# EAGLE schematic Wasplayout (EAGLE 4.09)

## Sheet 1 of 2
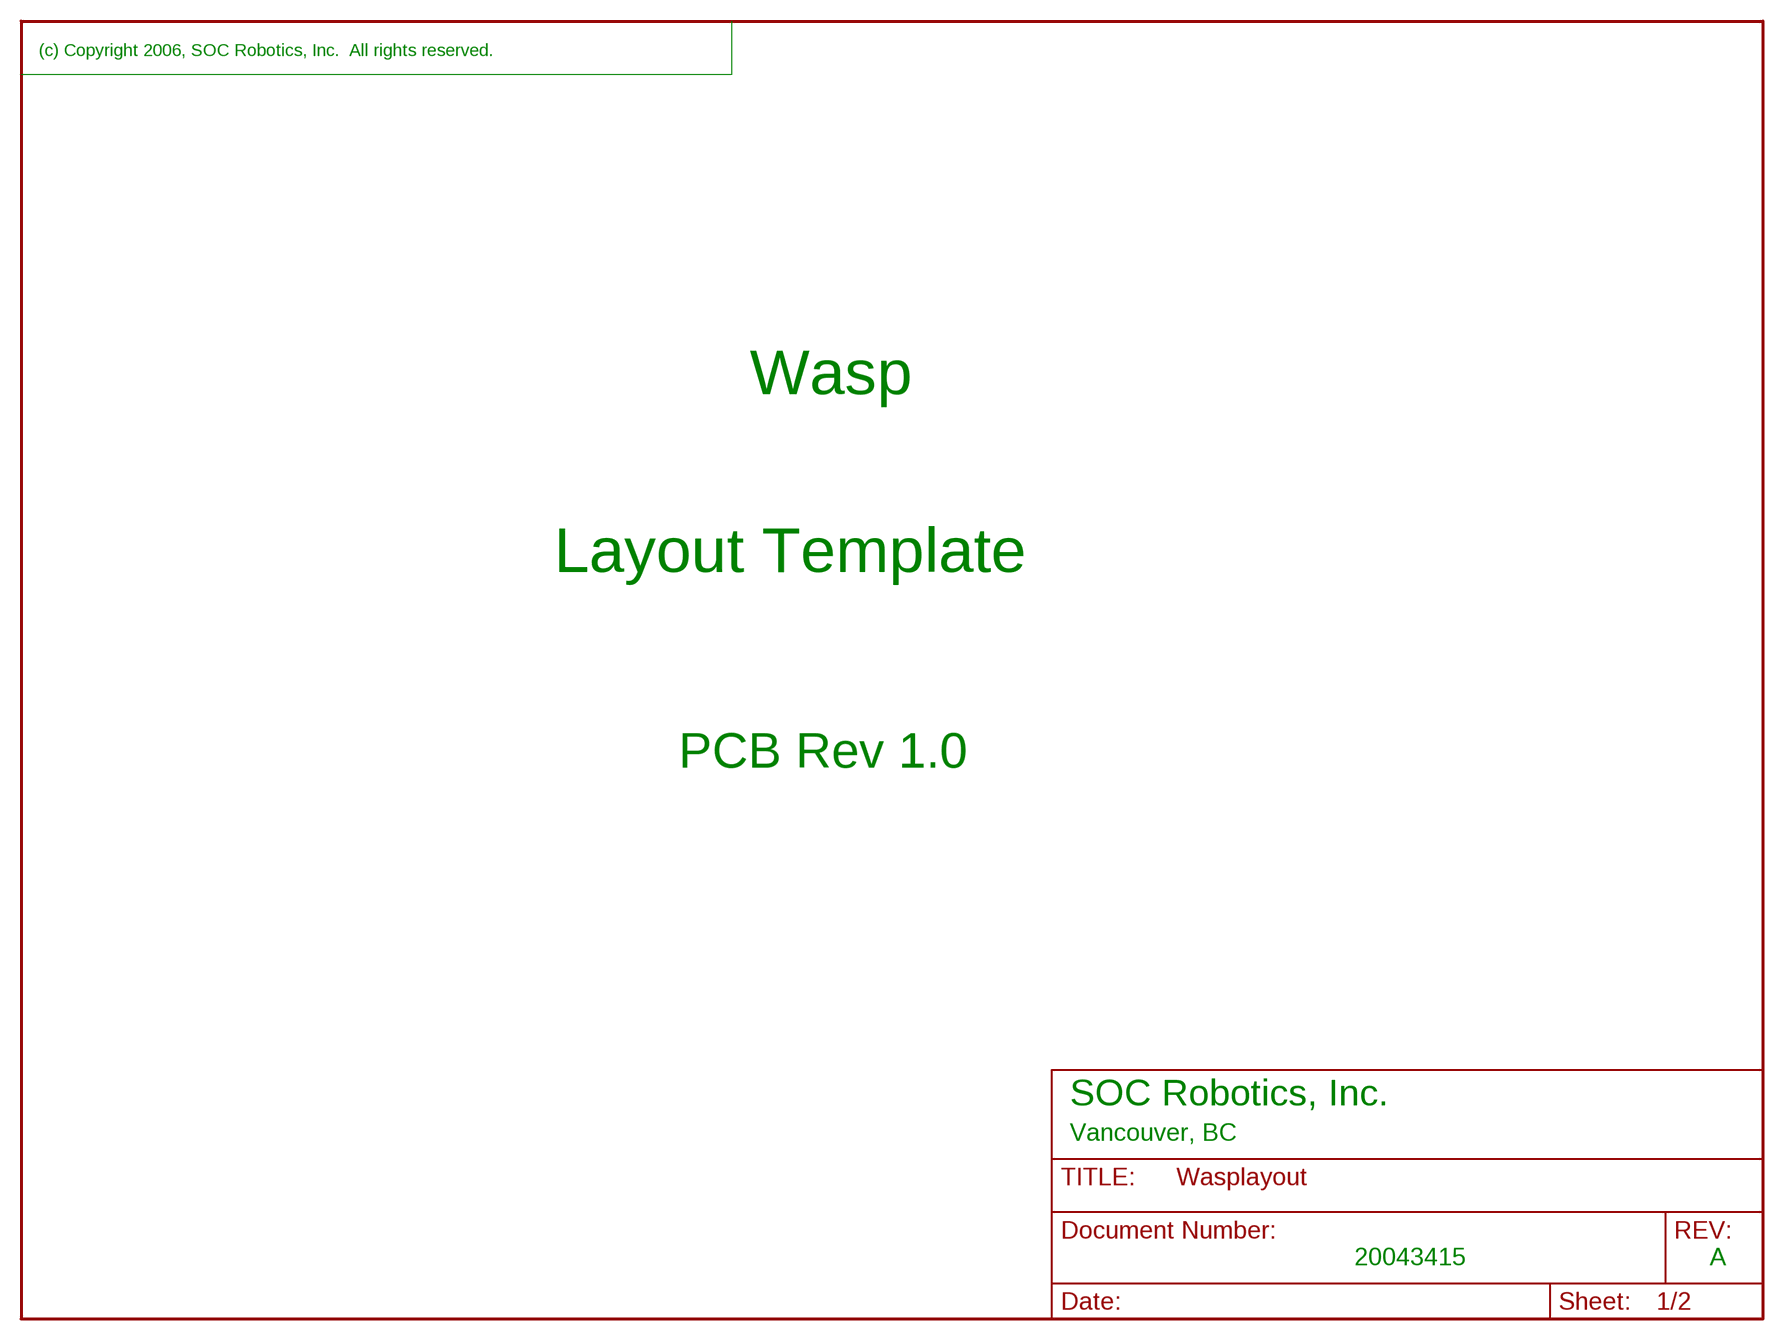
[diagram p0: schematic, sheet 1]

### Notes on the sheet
- (c) Copyright 2006, SOC Robotics, Inc.  All rights reserved.
- Wasp
- Layout Template
- PCB Rev 1.0
- SOC Robotics, Inc.
- Vancouver, BC
- 20043415 | A

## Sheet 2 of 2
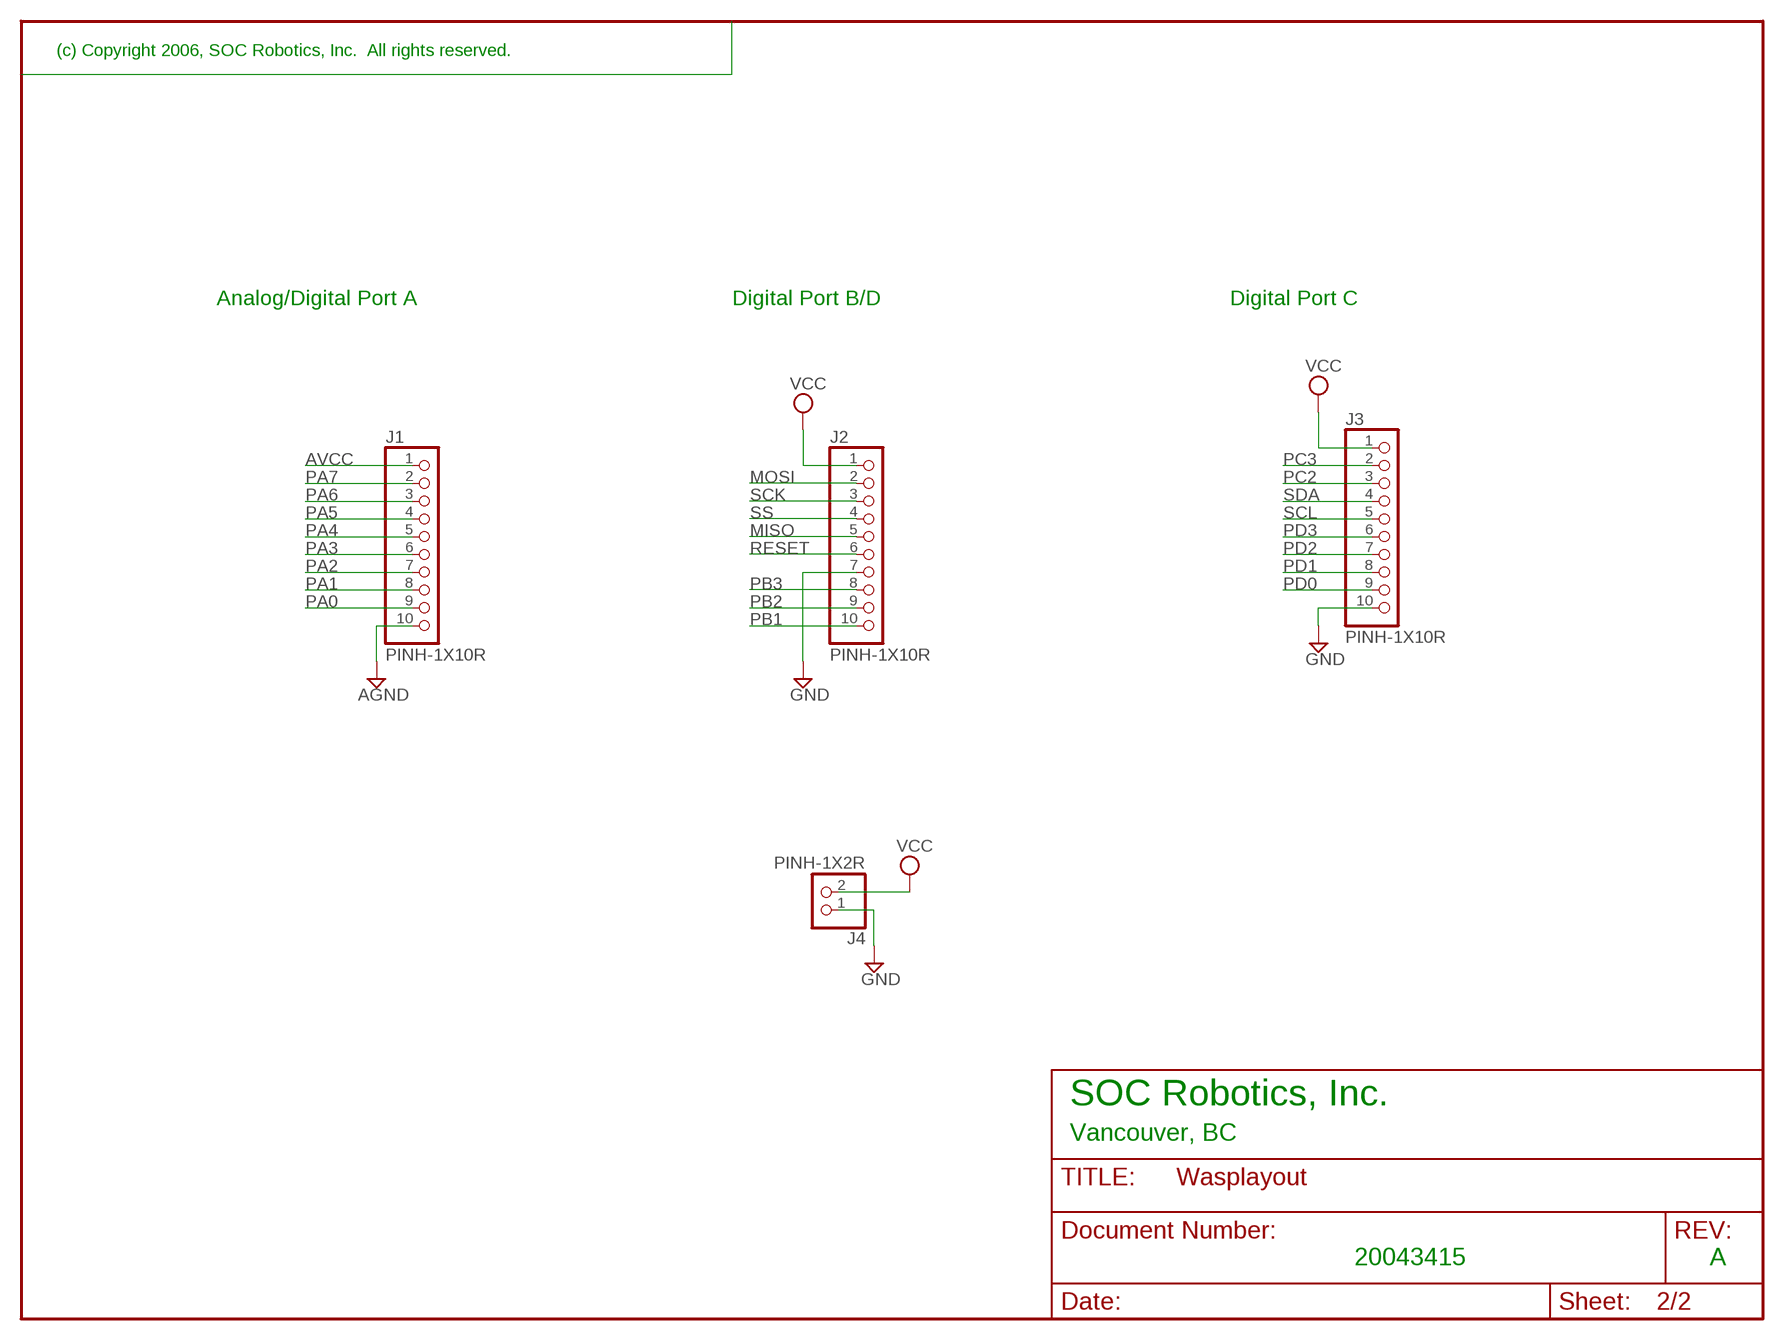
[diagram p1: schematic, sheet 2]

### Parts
J1  PINH-1X10R  [1X10ROUND]
J2  PINH-1X10R  [1X10ROUND]
J3  PINH-1X10R  [1X10ROUND]
J4  PINH-1X2R  PINH-1X2R"  [1X2ROUND]

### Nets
AGND: J1.10
AVCC: J1.1
GND: J2.7 J3.10 J4.1
MISO: J2.5
MOSI: J2.2
PA0: J1.9
PA1: J1.8
PA2: J1.7
PA3: J1.6
PA4: J1.5
PA5: J1.4
PA6: J1.3
PA7: J1.2
PB1: J2.10
PB2: J2.9
PB3: J2.8
PC2: J3.3
PC3: J3.2
PD0: J3.9
PD1: J3.8
PD2: J3.7
PD3: J3.6
RESET: J2.6
SCK: J2.3
SCL: J3.5
SDA: J3.4
SS: J2.4
VCC: J2.1 J3.1 J4.2

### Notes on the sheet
- (c) Copyright 2006, SOC Robotics, Inc.  All rights reserved.
- Analog/Digital Port A | Digital Port B/D | Digital Port C
- SOC Robotics, Inc.
- Vancouver, BC
- 20043415 | A

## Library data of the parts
J1-J3 = pinhead:PINH-1X10R
J4 = pinhead:PINH-1X2R: 1x2 Pin head round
